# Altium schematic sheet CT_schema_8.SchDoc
size 278 x 170 mm
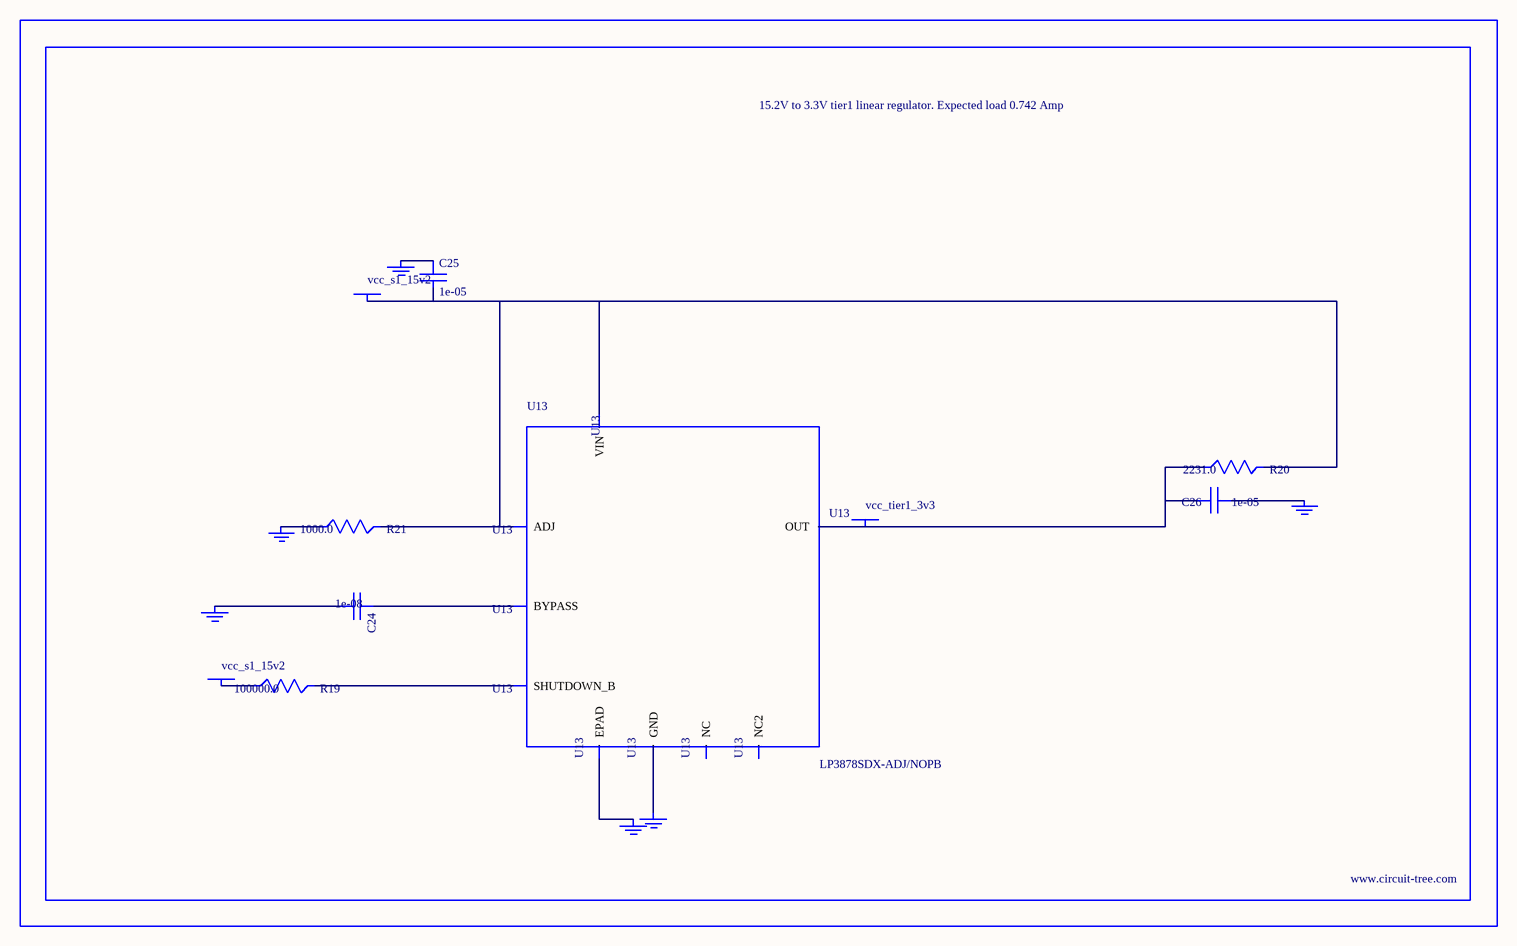
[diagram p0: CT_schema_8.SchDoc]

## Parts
BORDER7  (no value)
C24  1e-08  [C0402]
C25  1e-05  [C1210]
C26  1e-05  [C1210]
GND_INSTANCE_7_0  (no value)
GND_INSTANCE_7_1  (no value)
GND_INSTANCE_7_2  (no value)
GND_INSTANCE_7_3  (no value)
GND_INSTANCE_7_4  (no value)
GND_INSTANCE_7_5  (no value)
POWER_INSTANCE_7_0  vcc_s1_15v2
POWER_INSTANCE_7_1  vcc_s1_15v2
POWER_INSTANCE_7_2  vcc_tier1_3v3
R19  100000.0  [R0603]
R20  2231.0  [R0603]
R21  1000.0  [R0603]
U13  LP3878SDX-ADJ/NOPB  [WSON-8]

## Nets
NetC24_1: C24.1 U13.1(BYPASS)
NetC24_2: C24.2 GND_INSTANCE_7_0.0(GND)
NetC25_1: C25.1 GND_INSTANCE_7_1.0(GND)
NetC25_2: C25.2 POWER_INSTANCE_7_0.0(PWR) R20.2 R21.2 U13.4(VIN) U13.6(ADJ)
NetC26_1: C26.1 GND_INSTANCE_7_2.0(GND)
NetC26_2: C26.2 POWER_INSTANCE_7_2.0(PWR) R20.1 U13.5(OUT)
NetGND_INSTANCE_7_3_0: GND_INSTANCE_7_3.0(GND) R21.1
NetGND_INSTANCE_7_4_0: GND_INSTANCE_7_4.0(GND) U13.PAD(EPAD)
NetGND_INSTANCE_7_5_0: GND_INSTANCE_7_5.0(GND) U13.3(GND)
NetPOWER_INSTANCE_7_1_0: POWER_INSTANCE_7_1.0(PWR) R19.1
NetR19_2: R19.2 U13.8(SHUTDOWN_B)

Not connected (* = marked no-connect by the designer): U13 2(NC) 7(NC2)

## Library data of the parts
BORDER7 = BORDER_PAGE7
C24 = C0402C103K3RAC
C25 = C1210C106K5PACTU
C26 = GRM32DR61E106MA12L
GND_INSTANCE_7_0-GND_INSTANCE_7_5 = GND
POWER_INSTANCE_7_0-POWER_INSTANCE_7_2 = PWR
R19 = RC0603JR-07100KL
R20 = R20
R21 = RC0603JR-071KL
